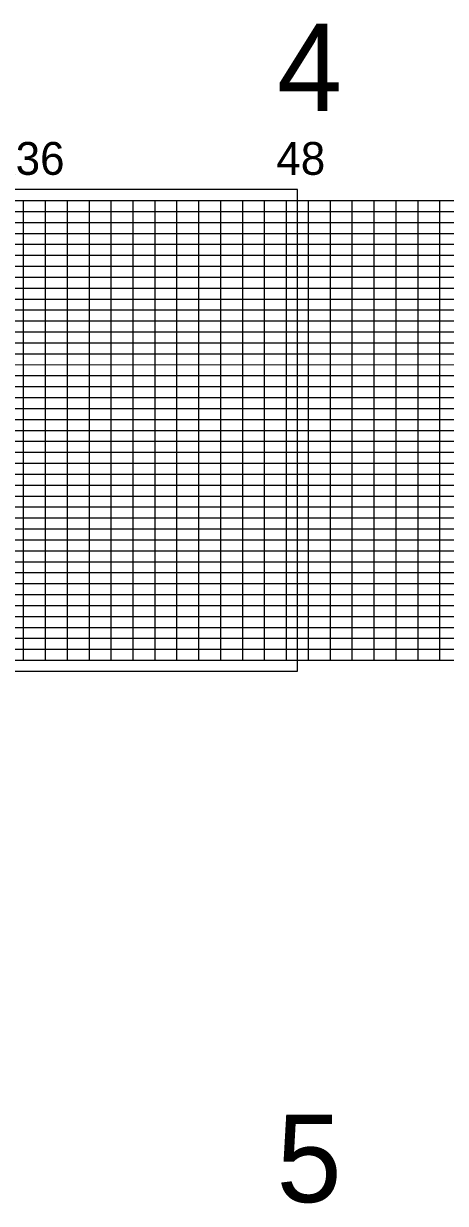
# Model space of a CAD drawing. Extents: x 1950433 to 1956806, y 750939 to 777666.
# Drawn here: x 1953106 to 1954069, y 767223 to 769918 of the extents above; entities that cross this region are included whole.
import ezdxf

# ---------------------------------------------------------------- set-up
doc = ezdxf.new("R2010")
doc.units = 0
for name, color, linetype in [('RD_PD_WallFill', 7, 'Continuous'), ('RD_SHT_IplotShp', 7, 'Continuous'), ('RD_Sketch8', 7, 'Continuous')]:
    doc.layers.add(name, color=color, linetype=linetype)

msp = doc.modelspace()

# ---------------------------------------------------------------- linework, layer by layer
at = {"layer": 'RD_PD_WallFill'}
for p, q in [((1951356.4, 769514.1), (1956706.4, 769514.1)), ((1953106.4, 768464.1), (1953106.4, 769514.1)), ((1953156.4, 768464.1), (1953156.4, 769514.1)), ((1953206.4, 768464.1), (1953206.4, 769514.1)), ((1953256.4, 768464.1), (1953256.4, 769514.1)), ((1953306.4, 768464.1), (1953306.4, 769514.1)), ((1953356.4, 768464.1), (1953356.4, 769514.1)), ((1953406.4, 768464.1), (1953406.4, 769514.1)), ((1953456.4, 768464.1), (1953456.4, 769514.1)), ((1953506.4, 768464.1), (1953506.4, 769514.1)), ((1953556.4, 768464.1), (1953556.4, 769514.1)), ((1953606.4, 768464.1), (1953606.4, 769514.1)), ((1953656.4, 768464.1), (1953656.4, 769514.1)), ((1953706.4, 768464.1), (1953706.4, 769514.1)), ((1953756.4, 768464.1), (1953756.4, 769514.1)), ((1953806.4, 768464.1), (1953806.4, 769514.1)), ((1953856.4, 768464.1), (1953856.4, 769514.1)), ((1953906.4, 768464.1), (1953906.4, 769514.1)), ((1953956.4, 768464.1), (1953956.4, 769514.1)), ((1954006.4, 768464.1), (1954006.4, 769514.1)), ((1954056.4, 768464.1), (1954056.4, 769514.1)), ((1951806.4, 769489.1), (1956706.4, 769489.1)), ((1951806.4, 769464.1), (1956706.4, 769464.1)), ((1951806.4, 769439.1), (1956706.4, 769439.1)), ((1951806.4, 769414.2), (1956706.4, 769414.1)), ((1951806.4, 769389.1), (1956706.4, 769389.2)), ((1951356.4, 769364.1), (1956706.4, 769364.1)), ((1951356.4, 769339.1), (1956706.4, 769339.1)), ((1951356.4, 769314.1), (1956706.4, 769314.2)), ((1951356.4, 769289.2), (1956706.4, 769289.1)), ((1951356.4, 769264.2), (1956706.4, 769264.2)), ((1951356.4, 769239.1), (1956706.4, 769239.1)), ((1951356.4, 769214.1), (1956706.4, 769214.1)), ((1951356.4, 769189.2), (1956706.4, 769189.1)), ((1951356.4, 769164.1), (1956706.4, 769164.1)), ((1951356.4, 769139.2), (1956706.4, 769139.1)), ((1951356.4, 769114.1), (1956706.4, 769114.1)), ((1951356.4, 769089.1), (1956706.4, 769089.2)), ((1951356.4, 769064.1), (1956706.4, 769064.1)), ((1951356.4, 769039.1), (1956706.4, 769039.2)), ((1951356.4, 769014.1), (1956706.4, 769014.1)), ((1951356.4, 768989.1), (1956706.4, 768989.1)), ((1951356.4, 768964.2), (1956706.4, 768964.1)), ((1951356.4, 768939.1), (1956706.4, 768939.1)), ((1951356.4, 768914.1), (1956706.4, 768914.1)), ((1951356.4, 768889.1), (1956706.4, 768889.1)), ((1951356.4, 768864.1), (1956706.4, 768864.2)), ((1951356.4, 768839.1), (1956706.4, 768839.1)), ((1951356.4, 768814.1), (1956706.4, 768814.1)), ((1951356.4, 768789.1), (1956706.4, 768789.1)), ((1951356.4, 768764.1), (1956706.4, 768764.1)), ((1951356.4, 768739.1), (1956706.4, 768739.1)), ((1951356.4, 768714.1), (1956706.4, 768714.1)), ((1951356.4, 768689.1), (1956706.4, 768689.1)), ((1951356.4, 768664.1), (1956706.4, 768664.1)), ((1951356.4, 768639.1), (1956706.4, 768639.1)), ((1951356.4, 768614.1), (1956706.4, 768614.1)), ((1951356.4, 768589.1), (1956706.4, 768589.1)), ((1951356.4, 768564.1), (1956706.4, 768564.1)), ((1951356.4, 768539.1), (1956706.4, 768539.1)), ((1951356.4, 768514.1), (1956706.4, 768514.1)), ((1951406.4, 768489.1), (1956706.4, 768489.1)), ((1951356.4, 768464.1), (1956706.4, 768464.1))]:
    msp.add_line(p, q, dxfattribs=at)
at = {"layer": 'RD_SHT_IplotShp'}
msp.add_lwpolyline([(1951331.4, 768439.1), (1953731.4, 768439.1), (1953731.4, 769539.1), (1951331.4, 769539.1)], close=True, dxfattribs=at)

# ---------------------------------------------------------------- texts
at = {"layer": 'RD_PD_WallFill'}
for s, p in [('22x36', (1952926.5, 769572.8)), ('48', (1953683.1, 769572.8))]:
    msp.add_text(s, height=75, dxfattribs=at).set_placement(p)
at = {"layer": 'RD_Sketch8'}
for s, p in [('4', (1953684.7, 769718.3)), ('5', (1953683.5, 767226.1))]:
    msp.add_text(s, height=200, dxfattribs=at).set_placement(p)

doc.saveas('drawing.dxf')
